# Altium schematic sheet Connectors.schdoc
size 49 x 56 mm
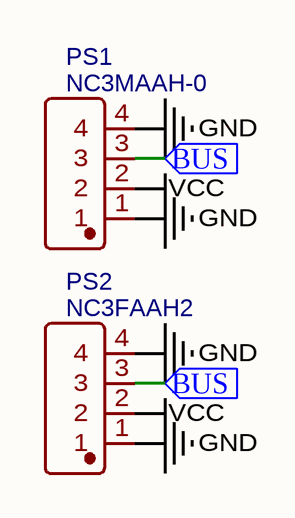
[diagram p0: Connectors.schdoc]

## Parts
PS1  NC3MAAH-0  [CONN-TH_NC3MAAH-0]
PS2  NC3FAAH2  [CONN-TH_NC3FAAH2]

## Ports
BUS (in)

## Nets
GND: PS1.1 PS1.4 PS2.1 PS2.4
VCC: PS1.2 PS2.2
BUS: PS1.3 PS2.3 ; port BUS

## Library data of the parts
PS1 = NC3MAAH-0: BOM_Manufacturer: Neutrik; Contributor: LCSC
PS2 = NC3FAAH2: BOM_Manufacturer: Neutrik; Contributor: LCSC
